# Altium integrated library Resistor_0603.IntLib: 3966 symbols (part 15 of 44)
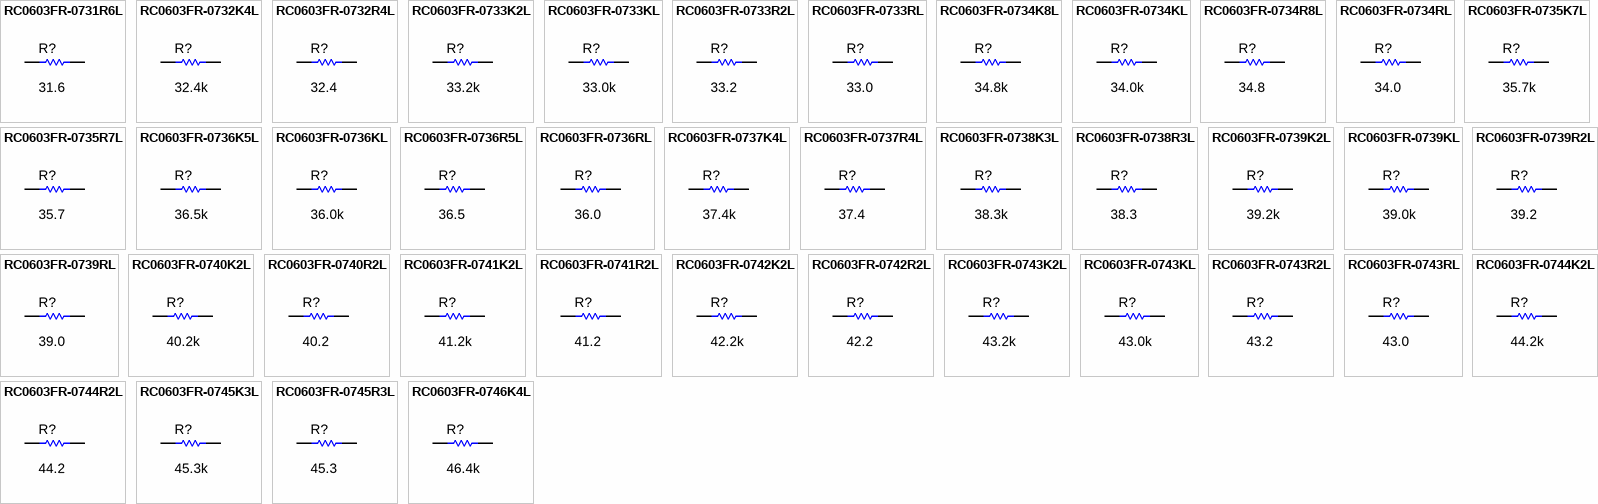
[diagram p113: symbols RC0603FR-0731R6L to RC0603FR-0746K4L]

## RC0603FR-0736RL
designator R?  ValueDisplayed: 36.0  (hidden comment: RC0603FR-0736RL)
RES, 36.0, 1%, 0.1 W, 0603; Manufacturer: Yageo America; CompType: Resistor; Value: 36.0; Res_ohm: 36; Value_Code: 36R0; Tolerance_%: 1; Power_W: 0.1; Value2: 0.1W; VDC_V: 150; TempCo: 200 ppm/C; SizeArea_mm2: 1.28; SizeX_mm: 1.6; SizeY_mm: 0.8; U/M: EA; AEC Category: Q200
signal-integrity model Resistor
simulation model Resistor
footprint 0603
footprint 0603M
footprint 0603L
footprint 0603_HV
footprint 0603S
pins: 1, 2

## RC0603FR-0737K4L
designator R?  ValueDisplayed: 37.4k  (hidden comment: RC0603FR-0737K4L)
RES, 37.4 k, 1%, 0.1 W, 0603; Manufacturer: Yageo America; CompType: Resistor; Value: 37.4k; Res_ohm: 37400; Value_Code: 37k4; Tolerance_%: 1; Power_W: 0.1; Value2: 0.1W; VDC_V: 150; TempCo: 200 ppm/C; SizeArea_mm2: 1.28; SizeX_mm: 1.6; SizeY_mm: 0.8; EIA_Code: E96; U/M: EA; AEC Category: Q200
signal-integrity model Resistor
simulation model Resistor
footprint 0603
footprint 0603M
footprint 0603L
footprint 0603_HV
footprint 0603S
pins: 1, 2

## RC0603FR-0737R4L
designator R?  ValueDisplayed: 37.4  (hidden comment: RC0603FR-0737R4L)
RES, 37.4, 1%, 0.1 W, 0603; Manufacturer: Yageo America; CompType: Resistor; Value: 37.4; Value_Code: 37R4; Tolerance_%: 1; Power_W: 0.1; Value2: 0.1W; VDC_V: 150; TempCo: 200 ppm/C; SizeArea_mm2: 1.28; SizeX_mm: 1.6; SizeY_mm: 0.8; EIA_Code: E96; U/M: EA; AEC Category: Q200
signal-integrity model Resistor
simulation model Resistor
footprint 0603
footprint 0603M
footprint 0603L
footprint 0603_HV
footprint 0603S
pins: 1, 2

## RC0603FR-0738K3L
designator R?  ValueDisplayed: 38.3k  (hidden comment: RC0603FR-0738K3L)
RES, 38.3 k, 1%, 0.1 W, 0603; Manufacturer: Yageo America; CompType: Resistor; Value: 38.3k; Res_ohm: 38300; Value_Code: 38k3; Tolerance_%: 1; Power_W: 0.1; Value2: 0.1W; VDC_V: 150; TempCo: 200 ppm/C; SizeArea_mm2: 1.28; SizeX_mm: 1.6; SizeY_mm: 0.8; EIA_Code: E96; U/M: EA; AEC Category: Q200; Green_Lifecycle: Active; Green_REACh: Passed
signal-integrity model Resistor
simulation model Resistor
footprint 0603
footprint 0603M
footprint 0603L
footprint 0603_HV
footprint 0603S
pins: 1, 2

## RC0603FR-0738R3L
designator R?  ValueDisplayed: 38.3  (hidden comment: RC0603FR-0738R3L)
RES, 38.3, 1%, 0.1 W, 0603; Manufacturer: Yageo America; CompType: Resistor; Value: 38.3; Value_Code: 38R3; Tolerance_%: 1; Power_W: 0.1; Value2: 0.1W; VDC_V: 150; TempCo: 200 ppm/C; SizeArea_mm2: 1.28; SizeX_mm: 1.6; SizeY_mm: 0.8; EIA_Code: E96; U/M: EA; AEC Category: Q200
signal-integrity model Resistor
simulation model Resistor
footprint 0603
footprint 0603M
footprint 0603L
footprint 0603_HV
footprint 0603S
pins: 1, 2

## RC0603FR-0739K2L
designator R?  ValueDisplayed: 39.2k  (hidden comment: RC0603FR-0739K2L)
RES, 39.2 k, 1%, 0.1 W, 0603; Manufacturer: Yageo America; CompType: Resistor; Value: 39.2k; Res_ohm: 39200; Value_Code: 39k2; Tolerance_%: 1; Power_W: 0.1; Value2: 0.1W; VDC_V: 150; TempCo: 200 ppm/C; SizeArea_mm2: 1.28; SizeX_mm: 1.6; SizeY_mm: 0.8; EIA_Code: E96; U/M: EA; AEC Category: Q200; Green_Lifecycle: Active; Green_REACh: Passed
signal-integrity model Resistor
simulation model Resistor
footprint 0603
footprint 0603M
footprint 0603L
footprint 0603_HV
footprint 0603S
pins: 1, 2

## RC0603FR-0739KL
designator R?  ValueDisplayed: 39.0k  (hidden comment: RC0603FR-0739KL)
RES, 39.0 k, 1%, 0.1 W, 0603; Manufacturer: Yageo America; CompType: Resistor; Value: 39.0k; Res_ohm: 39000; Value_Code: 39k0; Tolerance_%: 1; Power_W: 0.1; Value2: 0.1W; VDC_V: 150; TempCo: 200 ppm/C; SizeArea_mm2: 1.28; SizeX_mm: 1.6; SizeY_mm: 0.8; U/M: EA; AEC Category: Q200; Green_Lifecycle: Active; Green_REACh: Passed
signal-integrity model Resistor
simulation model Resistor
footprint 0603
footprint 0603M
footprint 0603L
footprint 0603_HV
footprint 0603S
pins: 1, 2

## RC0603FR-0739R2L
designator R?  ValueDisplayed: 39.2  (hidden comment: RC0603FR-0739R2L)
RES, 39.2, 1%, 0.1 W, 0603; Manufacturer: Yageo America; CompType: Resistor; Value: 39.2; Value_Code: 39R2; Tolerance_%: 1; Power_W: 0.1; Value2: 0.1W; VDC_V: 150; TempCo: 200 ppm/C; SizeArea_mm2: 1.28; SizeX_mm: 1.6; SizeY_mm: 0.8; EIA_Code: E96; U/M: EA; AEC Category: Q200
signal-integrity model Resistor
simulation model Resistor
footprint 0603
footprint 0603M
footprint 0603L
footprint 0603_HV
footprint 0603S
pins: 1, 2

## RC0603FR-0739RL
designator R?  ValueDisplayed: 39.0  (hidden comment: RC0603FR-0739RL)
RES, 39.0, 1%, 0.1 W, 0603; Manufacturer: Yageo America; CompType: Resistor; Value: 39.0; Res_ohm: 39; Value_Code: 39R0; Tolerance_%: 1; Power_W: 0.1; Value2: 0.1W; VDC_V: 150; TempCo: 200 ppm/C; SizeArea_mm2: 1.28; SizeX_mm: 1.6; SizeY_mm: 0.8; U/M: EA; AEC Category: Q200; Green_Lifecycle: Active; Green_REACh: Passed
signal-integrity model Resistor
simulation model Resistor
footprint 0603
footprint 0603M
footprint 0603L
footprint 0603_HV
footprint 0603S
pins: 1, 2

## RC0603FR-0740K2L
designator R?  ValueDisplayed: 40.2k  (hidden comment: RC0603FR-0740K2L)
RES, 40.2 k, 1%, 0.1 W, 0603; Manufacturer: Yageo America; CompType: Resistor; Value: 40.2k; Res_ohm: 40200; Value_Code: 40k2; Tolerance_%: 1; Power_W: 0.1; Value2: 0.1W; VDC_V: 150; TempCo: 200 ppm/C; SizeArea_mm2: 1.28; SizeX_mm: 1.6; SizeY_mm: 0.8; EIA_Code: E96; U/M: EA; AEC Category: Q200; Green_Lifecycle: Active; Green_REACh: Passed
signal-integrity model Resistor
simulation model Resistor
footprint 0603
footprint 0603M
footprint 0603L
footprint 0603_HV
footprint 0603S
pins: 1, 2

## RC0603FR-0740R2L
designator R?  ValueDisplayed: 40.2  (hidden comment: RC0603FR-0740R2L)
RES, 40.2, 1%, 0.1 W, 0603; Manufacturer: Yageo America; CompType: Resistor; Value: 40.2; Value_Code: 40R2; Tolerance_%: 1; Power_W: 0.1; Value2: 0.1W; VDC_V: 150; TempCo: 200 ppm/C; SizeArea_mm2: 1.28; SizeX_mm: 1.6; SizeY_mm: 0.8; EIA_Code: E96; U/M: EA; AEC Category: Q200
signal-integrity model Resistor
simulation model Resistor
footprint 0603
footprint 0603M
footprint 0603L
footprint 0603_HV
footprint 0603S
pins: 1, 2

## RC0603FR-0741K2L
designator R?  ValueDisplayed: 41.2k  (hidden comment: RC0603FR-0741K2L)
RES, 41.2 k, 1%, 0.1 W, 0603; Manufacturer: Yageo America; CompType: Resistor; Value: 41.2k; Res_ohm: 41200; Value_Code: 41k2; Tolerance_%: 1; Power_W: 0.1; Value2: 0.1W; VDC_V: 150; TempCo: 200 ppm/C; SizeArea_mm2: 1.28; SizeX_mm: 1.6; SizeY_mm: 0.8; EIA_Code: E96; U/M: EA; AEC Category: Q200; Green_Lifecycle: Active; Green_REACh: Passed
signal-integrity model Resistor
simulation model Resistor
footprint 0603
footprint 0603M
footprint 0603L
footprint 0603_HV
footprint 0603S
pins: 1, 2

## RC0603FR-0741R2L
designator R?  ValueDisplayed: 41.2  (hidden comment: RC0603FR-0741R2L)
RES, 41.2, 1%, 0.1 W, 0603; Manufacturer: Yageo America; CompType: Resistor; Value: 41.2; Value_Code: 41R2; Tolerance_%: 1; Power_W: 0.1; Value2: 0.1W; VDC_V: 150; TempCo: 200 ppm/C; SizeArea_mm2: 1.28; SizeX_mm: 1.6; SizeY_mm: 0.8; EIA_Code: E96; U/M: EA; AEC Category: Q200
signal-integrity model Resistor
simulation model Resistor
footprint 0603
footprint 0603M
footprint 0603L
footprint 0603_HV
footprint 0603S
pins: 1, 2

## RC0603FR-0742K2L
designator R?  ValueDisplayed: 42.2k  (hidden comment: RC0603FR-0742K2L)
RES, 42.2 k, 1%, 0.1 W, 0603; Manufacturer: Yageo America; CompType: Resistor; Value: 42.2k; Res_ohm: 42200; Value_Code: 42k2; Tolerance_%: 1; Power_W: 0.1; Value2: 0.1W; VDC_V: 150; TempCo: 200 ppm/C; SizeArea_mm2: 1.28; SizeX_mm: 1.6; SizeY_mm: 0.8; EIA_Code: E96; U/M: EA; AEC Category: Q200; Green_Lifecycle: Active; Green_REACh: Passed
signal-integrity model Resistor
simulation model Resistor
footprint 0603
footprint 0603M
footprint 0603L
footprint 0603_HV
footprint 0603S
pins: 1, 2

## RC0603FR-0742R2L
designator R?  ValueDisplayed: 42.2  (hidden comment: RC0603FR-0742R2L)
RES, 42.2, 1%, 0.1 W, 0603; Manufacturer: Yageo America; CompType: Resistor; Value: 42.2; Value_Code: 42R2; Tolerance_%: 1; Power_W: 0.1; Value2: 0.1W; VDC_V: 150; TempCo: 200 ppm/C; SizeArea_mm2: 1.28; SizeX_mm: 1.6; SizeY_mm: 0.8; EIA_Code: E96; U/M: EA; AEC Category: Q200
signal-integrity model Resistor
simulation model Resistor
footprint 0603
footprint 0603M
footprint 0603L
footprint 0603_HV
footprint 0603S
pins: 1, 2

## RC0603FR-0743K2L
designator R?  ValueDisplayed: 43.2k  (hidden comment: RC0603FR-0743K2L)
RES, 43.2 k, 1%, 0.1 W, 0603; Manufacturer: Yageo America; CompType: Resistor; Value: 43.2k; Res_ohm: 43200; Value_Code: 43k2; Tolerance_%: 1; Power_W: 0.1; Value2: 0.1W; VDC_V: 150; TempCo: 200 ppm/C; SizeArea_mm2: 1.28; SizeX_mm: 1.6; SizeY_mm: 0.8; EIA_Code: E96; U/M: EA; AEC Category: Q200; Green_Lifecycle: Active; Green_REACh: Passed
signal-integrity model Resistor
simulation model Resistor
footprint 0603
footprint 0603M
footprint 0603L
footprint 0603_HV
footprint 0603S
pins: 1, 2

## RC0603FR-0743KL
designator R?  ValueDisplayed: 43.0k  (hidden comment: RC0603FR-0743KL)
RES, 43.0 k, 1%, 0.1 W, 0603; Manufacturer: Yageo America; CompType: Resistor; Value: 43.0k; Res_ohm: 43000; Value_Code: 43k0; Tolerance_%: 1; Power_W: 0.1; Value2: 0.1W; VDC_V: 150; TempCo: 200 ppm/C; SizeArea_mm2: 1.28; SizeX_mm: 1.6; SizeY_mm: 0.8; U/M: EA; AEC Category: Q200; Green_Lifecycle: Active; Green_REACh: Passed
signal-integrity model Resistor
simulation model Resistor
footprint 0603
footprint 0603M
footprint 0603L
footprint 0603_HV
footprint 0603S
pins: 1, 2

## RC0603FR-0743R2L
designator R?  ValueDisplayed: 43.2  (hidden comment: RC0603FR-0743R2L)
RES, 43.2, 1%, 0.1 W, 0603; Manufacturer: Yageo America; CompType: Resistor; Value: 43.2; Value_Code: 43R2; Tolerance_%: 1; Power_W: 0.1; Value2: 0.1W; VDC_V: 150; TempCo: 200 ppm/C; SizeArea_mm2: 1.28; SizeX_mm: 1.6; SizeY_mm: 0.8; EIA_Code: E96; U/M: EA; AEC Category: Q200
signal-integrity model Resistor
simulation model Resistor
footprint 0603
footprint 0603M
footprint 0603L
footprint 0603_HV
footprint 0603S
pins: 1, 2

## RC0603FR-0743RL
designator R?  ValueDisplayed: 43.0  (hidden comment: RC0603FR-0743RL)
RES, 43.0, 1%, 0.1 W, 0603; Manufacturer: Yageo America; CompType: Resistor; Value: 43.0; Res_ohm: 43; Value_Code: 43R0; Tolerance_%: 1; Power_W: 0.1; Value2: 0.1W; VDC_V: 150; TempCo: 200 ppm/C; SizeArea_mm2: 1.28; SizeX_mm: 1.6; SizeY_mm: 0.8; U/M: EA; AEC Category: Q200; Green_Lifecycle: Active; Green_REACh: Passed
signal-integrity model Resistor
simulation model Resistor
footprint 0603
footprint 0603M
footprint 0603L
footprint 0603_HV
footprint 0603S
pins: 1, 2

## RC0603FR-0744K2L
designator R?  ValueDisplayed: 44.2k  (hidden comment: RC0603FR-0744K2L)
RES, 44.2 k, 1%, 0.1 W, 0603; Manufacturer: Yageo America; CompType: Resistor; Value: 44.2k; Res_ohm: 44200; Value_Code: 44k2; Tolerance_%: 1; Power_W: 0.1; Value2: 0.1W; VDC_V: 150; TempCo: 200 ppm/C; SizeArea_mm2: 1.28; SizeX_mm: 1.6; SizeY_mm: 0.8; EIA_Code: E96; U/M: EA; AEC Category: Q200; Green_Lifecycle: Active; Green_REACh: Passed
signal-integrity model Resistor
simulation model Resistor
footprint 0603
footprint 0603M
footprint 0603L
footprint 0603_HV
footprint 0603S
pins: 1, 2

## RC0603FR-0744R2L
designator R?  ValueDisplayed: 44.2  (hidden comment: RC0603FR-0744R2L)
RES, 44.2, 1%, 0.1 W, 0603; Manufacturer: Yageo America; CompType: Resistor; Value: 44.2; Value_Code: 44R2; Tolerance_%: 1; Power_W: 0.1; Value2: 0.1W; VDC_V: 150; TempCo: 200 ppm/C; SizeArea_mm2: 1.28; SizeX_mm: 1.6; SizeY_mm: 0.8; EIA_Code: E96; U/M: EA; AEC Category: Q200
signal-integrity model Resistor
simulation model Resistor
footprint 0603
footprint 0603M
footprint 0603L
footprint 0603_HV
footprint 0603S
pins: 1, 2

## RC0603FR-0745K3L
designator R?  ValueDisplayed: 45.3k  (hidden comment: RC0603FR-0745K3L)
RES, 45.3 k, 1%, 0.1 W, 0603; Manufacturer: Yageo America; CompType: Resistor; Value: 45.3k; Res_ohm: 45300; Value_Code: 45k3; Tolerance_%: 1; Power_W: 0.1; Value2: 0.1W; VDC_V: 150; TempCo: 200 ppm/C; SizeArea_mm2: 1.28; SizeX_mm: 1.6; SizeY_mm: 0.8; EIA_Code: E96; U/M: EA; AEC Category: Q200; Green_Lifecycle: Active; Green_REACh: Passed
signal-integrity model Resistor
simulation model Resistor
footprint 0603
footprint 0603M
footprint 0603L
footprint 0603_HV
footprint 0603S
pins: 1, 2

## RC0603FR-0745R3L
designator R?  ValueDisplayed: 45.3  (hidden comment: RC0603FR-0745R3L)
RES, 45.3, 1%, 0.1 W, 0603; Manufacturer: Yageo America; CompType: Resistor; Value: 45.3; Value_Code: 45R3; Tolerance_%: 1; Power_W: 0.1; Value2: 0.1W; VDC_V: 150; TempCo: 200 ppm/C; SizeArea_mm2: 1.28; SizeX_mm: 1.6; SizeY_mm: 0.8; EIA_Code: E96; U/M: EA; AEC Category: Q200
signal-integrity model Resistor
simulation model Resistor
footprint 0603
footprint 0603M
footprint 0603L
footprint 0603_HV
footprint 0603S
pins: 1, 2

## RC0603FR-0746K4L
designator R?  ValueDisplayed: 46.4k  (hidden comment: RC0603FR-0746K4L)
RES, 46.4 k, 1%, 0.1 W, 0603; Manufacturer: Yageo America; CompType: Resistor; Value: 46.4k; Res_ohm: 46400; Value_Code: 46k4; Tolerance_%: 1; Power_W: 0.1; Value2: 0.1W; VDC_V: 150; TempCo: 200 ppm/C; SizeArea_mm2: 1.28; SizeX_mm: 1.6; SizeY_mm: 0.8; EIA_Code: E96; U/M: EA; AEC Category: Q200; Green_Lifecycle: Active; Green_REACh: Passed
signal-integrity model Resistor
simulation model Resistor
footprint 0603
footprint 0603M
footprint 0603L
footprint 0603_HV
footprint 0603S
pins: 1, 2

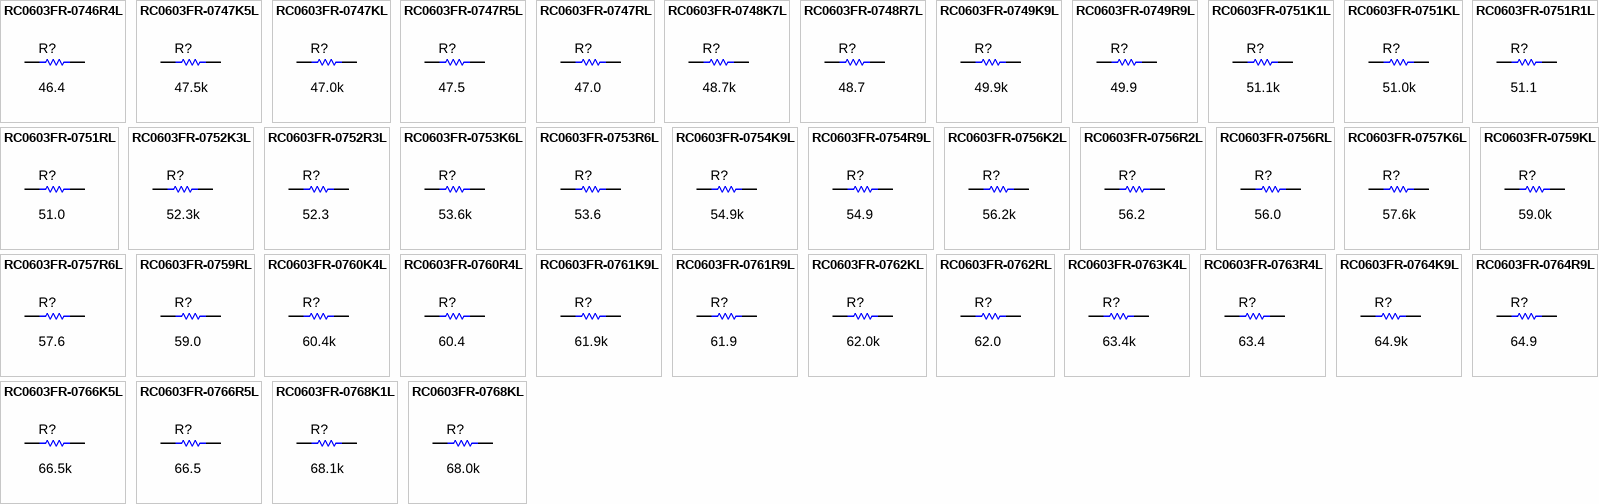
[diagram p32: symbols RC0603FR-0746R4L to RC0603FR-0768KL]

## RC0603FR-0746R4L
designator R?  ValueDisplayed: 46.4  (hidden comment: RC0603FR-0746R4L)
RES, 46.4, 1%, 0.1 W, 0603; Manufacturer: Yageo America; CompType: Resistor; Value: 46.4; Value_Code: 46R4; Tolerance_%: 1; Power_W: 0.1; Value2: 0.1W; VDC_V: 150; TempCo: 200 ppm/C; SizeArea_mm2: 1.28; SizeX_mm: 1.6; SizeY_mm: 0.8; EIA_Code: E96; U/M: EA; AEC Category: Q200
signal-integrity model Resistor
simulation model Resistor
footprint 0603
footprint 0603M
footprint 0603L
footprint 0603_HV
footprint 0603S
pins: 1, 2

## RC0603FR-0747K5L
designator R?  ValueDisplayed: 47.5k  (hidden comment: RC0603FR-0747K5L)
RES, 47.5 k, 1%, 0.1 W, 0603; Manufacturer: Yageo America; CompType: Resistor; Value: 47.5k; Res_ohm: 47500; Value_Code: 47k5; Tolerance_%: 1; Power_W: 0.1; Value2: 0.1W; VDC_V: 150; TempCo: 200 ppm/C; SizeArea_mm2: 1.28; SizeX_mm: 1.6; SizeY_mm: 0.8; EIA_Code: E96; U/M: EA; AEC Category: Q200; Green_Lifecycle: Active; Green_REACh: Passed
signal-integrity model Resistor
simulation model Resistor
footprint 0603
footprint 0603M
footprint 0603L
footprint 0603_HV
footprint 0603S
pins: 1, 2

## RC0603FR-0747KL
designator R?  ValueDisplayed: 47.0k  (hidden comment: RC0603FR-0747KL)
RES, 47.0 k, 1%, 0.1 W, 0603; Manufacturer: Yageo America; CompType: Resistor; Value: 47.0k; Res_ohm: 47000; Value_Code: 47k0; Tolerance_%: 1; Power_W: 0.1; Value2: 0.1W; VDC_V: 150; TempCo: 200 ppm/C; SizeArea_mm2: 1.28; SizeX_mm: 1.6; SizeY_mm: 0.8; U/M: EA; AEC Category: Q200; Green_Lifecycle: Active; Green_REACh: Passed
signal-integrity model Resistor
simulation model Resistor
footprint 0603
footprint 0603M
footprint 0603L
footprint 0603_HV
footprint 0603S
pins: 1, 2

## RC0603FR-0747R5L
designator R?  ValueDisplayed: 47.5  (hidden comment: RC0603FR-0747R5L)
RES, 47.5, 1%, 0.1 W, 0603; Manufacturer: Yageo America; CompType: Resistor; Value: 47.5; Value_Code: 47R5; Tolerance_%: 1; Power_W: 0.1; Value2: 0.1W; VDC_V: 150; TempCo: 200 ppm/C; SizeArea_mm2: 1.28; SizeX_mm: 1.6; SizeY_mm: 0.8; EIA_Code: E96; U/M: EA; AEC Category: Q200
signal-integrity model Resistor
simulation model Resistor
footprint 0603
footprint 0603M
footprint 0603L
footprint 0603_HV
footprint 0603S
pins: 1, 2

## RC0603FR-0747RL
designator R?  ValueDisplayed: 47.0  (hidden comment: RC0603FR-0747RL)
RES, 47.0, 1%, 0.1 W, 0603; Manufacturer: Yageo America; CompType: Resistor; Value: 47.0; Res_ohm: 47; Value_Code: 47R0; Tolerance_%: 1; Power_W: 0.1; Value2: 0.1W; VDC_V: 150; TempCo: 200 ppm/C; SizeArea_mm2: 1.28; SizeX_mm: 1.6; SizeY_mm: 0.8; U/M: EA; AEC Category: Q200; Green_Lifecycle: Active; Green_REACh: Passed
signal-integrity model Resistor
simulation model Resistor
footprint 0603
footprint 0603M
footprint 0603L
footprint 0603_HV
footprint 0603S
pins: 1, 2

## RC0603FR-0748K7L
designator R?  ValueDisplayed: 48.7k  (hidden comment: RC0603FR-0748K7L)
RES, 48.7 k, 1%, 0.1 W, 0603; Manufacturer: Yageo America; CompType: Resistor; Value: 48.7k; Res_ohm: 48700; Value_Code: 48k7; Tolerance_%: 1; Power_W: 0.1; Value2: 0.1W; VDC_V: 150; TempCo: 200 ppm/C; SizeArea_mm2: 1.28; SizeX_mm: 1.6; SizeY_mm: 0.8; EIA_Code: E96; U/M: EA; AEC Category: Q200; Green_Lifecycle: Active; Green_REACh: Passed
signal-integrity model Resistor
simulation model Resistor
footprint 0603
footprint 0603M
footprint 0603L
footprint 0603_HV
footprint 0603S
pins: 1, 2

## RC0603FR-0748R7L
designator R?  ValueDisplayed: 48.7  (hidden comment: RC0603FR-0748R7L)
RES, 48.7, 1%, 0.1 W, 0603; Manufacturer: Yageo America; CompType: Resistor; Value: 48.7; Value_Code: 48R7; Tolerance_%: 1; Power_W: 0.1; Value2: 0.1W; VDC_V: 150; TempCo: 200 ppm/C; SizeArea_mm2: 1.28; SizeX_mm: 1.6; SizeY_mm: 0.8; EIA_Code: E96; U/M: EA; AEC Category: Q200
signal-integrity model Resistor
simulation model Resistor
footprint 0603
footprint 0603M
footprint 0603L
footprint 0603_HV
footprint 0603S
pins: 1, 2

## RC0603FR-0749K9L
designator R?  ValueDisplayed: 49.9k  (hidden comment: RC0603FR-0749K9L)
RES, 49.9 k, 1%, 0.1 W, 0603; Manufacturer: Yageo America; CompType: Resistor; Value: 49.9k; Res_ohm: 49900; Value_Code: 49k9; Tolerance_%: 1; Power_W: 0.1; Value2: 0.1W; VDC_V: 150; TempCo: 200 ppm/C; SizeArea_mm2: 1.28; SizeX_mm: 1.6; SizeY_mm: 0.8; EIA_Code: E96; U/M: EA; AEC Category: Q200; Green_Lifecycle: Active; Green_REACh: Passed
signal-integrity model Resistor
simulation model Resistor
footprint 0603
footprint 0603M
footprint 0603L
footprint 0603_HV
footprint 0603S
pins: 1, 2

## RC0603FR-0749R9L
designator R?  ValueDisplayed: 49.9  (hidden comment: RC0603FR-0749R9L)
RES, 49.9, 1%, 0.1 W, 0603; Manufacturer: Yageo America; CompType: Resistor; Value: 49.9; Value_Code: 49R9; Tolerance_%: 1; Power_W: 0.1; Value2: 0.1W; VDC_V: 150; TempCo: 200 ppm/C; SizeArea_mm2: 1.28; SizeX_mm: 1.6; SizeY_mm: 0.8; EIA_Code: E96; U/M: EA; AEC Category: Q200; Green_Lifecycle: Active; Green_REACh: Passed
signal-integrity model Resistor
simulation model Resistor
footprint 0603
footprint 0603M
footprint 0603L
footprint 0603_HV
footprint 0603S
pins: 1, 2

## RC0603FR-0751K1L
designator R?  ValueDisplayed: 51.1k  (hidden comment: RC0603FR-0751K1L)
RES, 51.1 k, 1%, 0.1 W, 0603; Manufacturer: Yageo America; CompType: Resistor; Value: 51.1k; Res_ohm: 51100; Value_Code: 51k1; Tolerance_%: 1; Power_W: 0.1; Value2: 0.1W; VDC_V: 150; TempCo: 200 ppm/C; SizeArea_mm2: 1.28; SizeX_mm: 1.6; SizeY_mm: 0.8; EIA_Code: E96; U/M: EA; AEC Category: Q200; Green_Lifecycle: Active; Green_REACh: Passed
signal-integrity model Resistor
simulation model Resistor
footprint 0603
footprint 0603M
footprint 0603L
footprint 0603_HV
footprint 0603S
pins: 1, 2

## RC0603FR-0751KL
designator R?  ValueDisplayed: 51.0k  (hidden comment: RC0603FR-0751KL)
RES, 51.0 k, 1%, 0.1 W, 0603; Manufacturer: Yageo America; CompType: Resistor; Value: 51.0k; Res_ohm: 51000; Value_Code: 51k0; Tolerance_%: 1; Power_W: 0.1; Value2: 0.1W; VDC_V: 150; TempCo: 200 ppm/C; SizeArea_mm2: 1.28; SizeX_mm: 1.6; SizeY_mm: 0.8; U/M: EA; AEC Category: Q200; Green_Lifecycle: Active; Green_REACh: Passed
signal-integrity model Resistor
simulation model Resistor
footprint 0603
footprint 0603M
footprint 0603L
footprint 0603_HV
footprint 0603S
pins: 1, 2

## RC0603FR-0751R1L
designator R?  ValueDisplayed: 51.1  (hidden comment: RC0603FR-0751R1L)
RES, 51.1, 1%, 0.1 W, 0603; Manufacturer: Yageo America; CompType: Resistor; Value: 51.1; Value_Code: 51R1; Tolerance_%: 1; Power_W: 0.1; Value2: 0.1W; VDC_V: 150; TempCo: 200 ppm/C; SizeArea_mm2: 1.28; SizeX_mm: 1.6; SizeY_mm: 0.8; EIA_Code: E96; U/M: EA; AEC Category: Q200; Green_Lifecycle: Active; Green_REACh: Passed
signal-integrity model Resistor
simulation model Resistor
footprint 0603
footprint 0603M
footprint 0603L
footprint 0603_HV
footprint 0603S
pins: 1, 2

## RC0603FR-0751RL
designator R?  ValueDisplayed: 51.0  (hidden comment: RC0603FR-0751RL)
RES, 51.0, 1%, 0.1 W, 0603; Manufacturer: Yageo America; CompType: Resistor; Value: 51.0; Res_ohm: 51; Value_Code: 51R0; Tolerance_%: 1; Power_W: 0.1; Value2: 0.1W; VDC_V: 150; TempCo: 200 ppm/C; SizeArea_mm2: 1.28; SizeX_mm: 1.6; SizeY_mm: 0.8; U/M: EA; AEC Category: Q200; Green_Lifecycle: Active; Green_REACh: Passed
signal-integrity model Resistor
simulation model Resistor
footprint 0603
footprint 0603M
footprint 0603L
footprint 0603_HV
footprint 0603S
pins: 1, 2

## RC0603FR-0752K3L
designator R?  ValueDisplayed: 52.3k  (hidden comment: RC0603FR-0752K3L)
RES, 52.3 k, 1%, 0.1 W, 0603; Manufacturer: Yageo America; CompType: Resistor; Value: 52.3k; Res_ohm: 52300; Value_Code: 52k3; Tolerance_%: 1; Power_W: 0.1; Value2: 0.1W; VDC_V: 150; TempCo: 200 ppm/C; SizeArea_mm2: 1.28; SizeX_mm: 1.6; SizeY_mm: 0.8; EIA_Code: E96; U/M: EA; AEC Category: Q200; Green_Lifecycle: Active; Green_REACh: Passed
signal-integrity model Resistor
simulation model Resistor
footprint 0603
footprint 0603M
footprint 0603L
footprint 0603_HV
footprint 0603S
pins: 1, 2

## RC0603FR-0752R3L
designator R?  ValueDisplayed: 52.3  (hidden comment: RC0603FR-0752R3L)
RES, 52.3, 1%, 0.1 W, 0603; Manufacturer: Yageo America; CompType: Resistor; Value: 52.3; Value_Code: 52R3; Tolerance_%: 1; Power_W: 0.1; Value2: 0.1W; VDC_V: 150; TempCo: 200 ppm/C; SizeArea_mm2: 1.28; SizeX_mm: 1.6; SizeY_mm: 0.8; EIA_Code: E96; U/M: EA; AEC Category: Q200
signal-integrity model Resistor
simulation model Resistor
footprint 0603
footprint 0603M
footprint 0603L
footprint 0603_HV
footprint 0603S
pins: 1, 2

## RC0603FR-0753K6L
designator R?  ValueDisplayed: 53.6k  (hidden comment: RC0603FR-0753K6L)
RES, 53.6 k, 1%, 0.1 W, 0603; Manufacturer: Yageo America; CompType: Resistor; Value: 53.6k; Res_ohm: 53600; Value_Code: 53k6; Tolerance_%: 1; Power_W: 0.1; Value2: 0.1W; VDC_V: 150; TempCo: 200 ppm/C; SizeArea_mm2: 1.28; SizeX_mm: 1.6; SizeY_mm: 0.8; EIA_Code: E96; U/M: EA; AEC Category: Q200; Green_Lifecycle: Active; Green_REACh: Passed
signal-integrity model Resistor
simulation model Resistor
footprint 0603
footprint 0603M
footprint 0603L
footprint 0603_HV
footprint 0603S
pins: 1, 2

## RC0603FR-0753R6L
designator R?  ValueDisplayed: 53.6  (hidden comment: RC0603FR-0753R6L)
RES, 53.6, 1%, 0.1 W, 0603; Manufacturer: Yageo America; CompType: Resistor; Value: 53.6; Value_Code: 53R6; Tolerance_%: 1; Power_W: 0.1; Value2: 0.1W; VDC_V: 150; TempCo: 200 ppm/C; SizeArea_mm2: 1.28; SizeX_mm: 1.6; SizeY_mm: 0.8; EIA_Code: E96; U/M: EA; AEC Category: Q200
signal-integrity model Resistor
simulation model Resistor
footprint 0603
footprint 0603M
footprint 0603L
footprint 0603_HV
footprint 0603S
pins: 1, 2

## RC0603FR-0754K9L
designator R?  ValueDisplayed: 54.9k  (hidden comment: RC0603FR-0754K9L)
RES, 54.9 k, 1%, 0.1 W, 0603; Manufacturer: Yageo America; CompType: Resistor; Value: 54.9k; Res_ohm: 54900; Value_Code: 54k9; Tolerance_%: 1; Power_W: 0.1; Value2: 0.1W; VDC_V: 150; TempCo: 200 ppm/C; SizeArea_mm2: 1.28; SizeX_mm: 1.6; SizeY_mm: 0.8; EIA_Code: E96; U/M: EA; AEC Category: Q200
signal-integrity model Resistor
simulation model Resistor
footprint 0603
footprint 0603M
footprint 0603L
footprint 0603_HV
footprint 0603S
pins: 1, 2

## RC0603FR-0754R9L
designator R?  ValueDisplayed: 54.9  (hidden comment: RC0603FR-0754R9L)
RES, 54.9, 1%, 0.1 W, 0603; Manufacturer: Yageo America; CompType: Resistor; Value: 54.9; Value_Code: 54R9; Tolerance_%: 1; Power_W: 0.1; Value2: 0.1W; VDC_V: 150; TempCo: 200 ppm/C; SizeArea_mm2: 1.28; SizeX_mm: 1.6; SizeY_mm: 0.8; EIA_Code: E96; U/M: EA; AEC Category: Q200; Green_Lifecycle: Active; Green_REACh: Passed
signal-integrity model Resistor
simulation model Resistor
footprint 0603
footprint 0603M
footprint 0603L
footprint 0603_HV
footprint 0603S
pins: 1, 2

## RC0603FR-0756K2L
designator R?  ValueDisplayed: 56.2k  (hidden comment: RC0603FR-0756K2L)
RES, 56.2 k, 1%, 0.1 W, 0603; Manufacturer: Yageo America; CompType: Resistor; Value: 56.2k; Res_ohm: 56200; Value_Code: 56k2; Tolerance_%: 1; Power_W: 0.1; Value2: 0.1W; VDC_V: 150; TempCo: 200 ppm/C; SizeArea_mm2: 1.28; SizeX_mm: 1.6; SizeY_mm: 0.8; EIA_Code: E96; U/M: EA; AEC Category: Q200; Green_Lifecycle: Active; Green_REACh: Passed
signal-integrity model Resistor
simulation model Resistor
footprint 0603
footprint 0603M
footprint 0603L
footprint 0603_HV
footprint 0603S
pins: 1, 2

## RC0603FR-0756R2L
designator R?  ValueDisplayed: 56.2  (hidden comment: RC0603FR-0756R2L)
RES, 56.2, 1%, 0.1 W, 0603; Manufacturer: Yageo America; CompType: Resistor; Value: 56.2; Value_Code: 56R2; Tolerance_%: 1; Power_W: 0.1; Value2: 0.1W; VDC_V: 150; TempCo: 200 ppm/C; SizeArea_mm2: 1.28; SizeX_mm: 1.6; SizeY_mm: 0.8; EIA_Code: E96; U/M: EA; AEC Category: Q200
signal-integrity model Resistor
simulation model Resistor
footprint 0603
footprint 0603M
footprint 0603L
footprint 0603_HV
footprint 0603S
pins: 1, 2

## RC0603FR-0756RL
designator R?  ValueDisplayed: 56.0  (hidden comment: RC0603FR-0756RL)
RES, 56.0, 1%, 0.1 W, 0603; Manufacturer: Yageo America; CompType: Resistor; Value: 56.0; Res_ohm: 56; Value_Code: 56R0; Tolerance_%: 1; Power_W: 0.1; Value2: 0.1W; VDC_V: 150; TempCo: 200 ppm/C; SizeArea_mm2: 1.28; SizeX_mm: 1.6; SizeY_mm: 0.8; U/M: EA; AEC Category: Q200; Green_Lifecycle: Active; Green_REACh: Passed
signal-integrity model Resistor
simulation model Resistor
footprint 0603
footprint 0603M
footprint 0603L
footprint 0603_HV
footprint 0603S
pins: 1, 2

## RC0603FR-0757K6L
designator R?  ValueDisplayed: 57.6k  (hidden comment: RC0603FR-0757K6L)
RES, 57.6 k, 1%, 0.1 W, 0603; Manufacturer: Yageo America; CompType: Resistor; Value: 57.6k; Res_ohm: 57600; Value_Code: 57k6; Tolerance_%: 1; Power_W: 0.1; Value2: 0.1W; VDC_V: 150; TempCo: 200 ppm/C; SizeArea_mm2: 1.28; SizeX_mm: 1.6; SizeY_mm: 0.8; EIA_Code: E96; U/M: EA; AEC Category: Q200; Green_Lifecycle: Active; Green_REACh: Passed
signal-integrity model Resistor
simulation model Resistor
footprint 0603
footprint 0603M
footprint 0603L
footprint 0603_HV
footprint 0603S
pins: 1, 2

## RC0603FR-0757R6L
designator R?  ValueDisplayed: 57.6  (hidden comment: RC0603FR-0757R6L)
RES, 57.6, 1%, 0.1 W, 0603; Manufacturer: Yageo America; CompType: Resistor; Value: 57.6; Value_Code: 57R6; Tolerance_%: 1; Power_W: 0.1; Value2: 0.1W; VDC_V: 150; TempCo: 200 ppm/C; SizeArea_mm2: 1.28; SizeX_mm: 1.6; SizeY_mm: 0.8; EIA_Code: E96; U/M: EA; AEC Category: Q200
signal-integrity model Resistor
simulation model Resistor
footprint 0603
footprint 0603M
footprint 0603L
footprint 0603_HV
footprint 0603S
pins: 1, 2

## RC0603FR-0759KL
designator R?  ValueDisplayed: 59.0k  (hidden comment: RC0603FR-0759KL)
RES, 59.0 k, 1%, 0.1 W, 0603; Manufacturer: Yageo America; CompType: Resistor; Value: 59.0k; Res_ohm: 59000; Value_Code: 59k0; Tolerance_%: 1; Power_W: 0.1; Value2: 0.1W; VDC_V: 150; TempCo: 200 ppm/C; SizeArea_mm2: 1.28; SizeX_mm: 1.6; SizeY_mm: 0.8; EIA_Code: E96; U/M: EA; AEC Category: Q200; Green_Lifecycle: Active; Green_REACh: Passed
signal-integrity model Resistor
simulation model Resistor
footprint 0603
footprint 0603M
footprint 0603L
footprint 0603_HV
footprint 0603S
pins: 1, 2

## RC0603FR-0759RL
designator R?  ValueDisplayed: 59.0  (hidden comment: RC0603FR-0759RL)
RES, 59.0, 1%, 0.1 W, 0603; Manufacturer: Yageo America; CompType: Resistor; Value: 59.0; Res_ohm: 59; Value_Code: 59R0; Tolerance_%: 1; Power_W: 0.1; Value2: 0.1W; VDC_V: 150; TempCo: 200 ppm/C; SizeArea_mm2: 1.28; SizeX_mm: 1.6; SizeY_mm: 0.8; EIA_Code: E96; U/M: EA; AEC Category: Q200
signal-integrity model Resistor
simulation model Resistor
footprint 0603
footprint 0603M
footprint 0603L
footprint 0603_HV
footprint 0603S
pins: 1, 2

## RC0603FR-0760K4L
designator R?  ValueDisplayed: 60.4k  (hidden comment: RC0603FR-0760K4L)
RES, 60.4 k, 1%, 0.1 W, 0603; Manufacturer: Yageo America; CompType: Resistor; Value: 60.4k; Res_ohm: 60400; Value_Code: 60k4; Tolerance_%: 1; Power_W: 0.1; Value2: 0.1W; VDC_V: 150; TempCo: 200 ppm/C; SizeArea_mm2: 1.28; SizeX_mm: 1.6; SizeY_mm: 0.8; EIA_Code: E96; U/M: EA; AEC Category: Q200; Green_Lifecycle: Active; Green_REACh: Passed
signal-integrity model Resistor
simulation model Resistor
footprint 0603
footprint 0603M
footprint 0603L
footprint 0603_HV
footprint 0603S
pins: 1, 2

## RC0603FR-0760R4L
designator R?  ValueDisplayed: 60.4  (hidden comment: RC0603FR-0760R4L)
RES, 60.4, 1%, 0.1 W, 0603; Manufacturer: Yageo America; CompType: Resistor; Value: 60.4; Value_Code: 60R4; Tolerance_%: 1; Power_W: 0.1; Value2: 0.1W; VDC_V: 150; TempCo: 200 ppm/C; SizeArea_mm2: 1.28; SizeX_mm: 1.6; SizeY_mm: 0.8; EIA_Code: E96; U/M: EA; AEC Category: Q200
signal-integrity model Resistor
simulation model Resistor
footprint 0603
footprint 0603M
footprint 0603L
footprint 0603_HV
footprint 0603S
pins: 1, 2

## RC0603FR-0761K9L
designator R?  ValueDisplayed: 61.9k  (hidden comment: RC0603FR-0761K9L)
RES, 61.9 k, 1%, 0.1 W, 0603; Manufacturer: Yageo America; CompType: Resistor; Value: 61.9k; Res_ohm: 61900; Value_Code: 61k9; Tolerance_%: 1; Power_W: 0.1; Value2: 0.1W; VDC_V: 150; TempCo: 200 ppm/C; SizeArea_mm2: 1.28; SizeX_mm: 1.6; SizeY_mm: 0.8; EIA_Code: E96; U/M: EA; AEC Category: Q200
signal-integrity model Resistor
simulation model Resistor
footprint 0603
footprint 0603M
footprint 0603L
footprint 0603_HV
footprint 0603S
pins: 1, 2

## RC0603FR-0761R9L
designator R?  ValueDisplayed: 61.9  (hidden comment: RC0603FR-0761R9L)
RES, 61.9, 1%, 0.1 W, 0603; Manufacturer: Yageo America; CompType: Resistor; Value: 61.9; Value_Code: 61R9; Tolerance_%: 1; Power_W: 0.1; Value2: 0.1W; VDC_V: 150; TempCo: 200 ppm/C; SizeArea_mm2: 1.28; SizeX_mm: 1.6; SizeY_mm: 0.8; EIA_Code: E96; U/M: EA; AEC Category: Q200
signal-integrity model Resistor
simulation model Resistor
footprint 0603
footprint 0603M
footprint 0603L
footprint 0603_HV
footprint 0603S
pins: 1, 2

## RC0603FR-0762KL
designator R?  ValueDisplayed: 62.0k  (hidden comment: RC0603FR-0762KL)
RES, 62.0 k, 1%, 0.1 W, 0603; Manufacturer: Yageo America; CompType: Resistor; Value: 62.0k; Res_ohm: 62000; Value_Code: 62k0; Tolerance_%: 1; Power_W: 0.1; Value2: 0.1W; VDC_V: 150; TempCo: 200 ppm/C; SizeArea_mm2: 1.28; SizeX_mm: 1.6; SizeY_mm: 0.8; U/M: EA; AEC Category: Q200; Green_Lifecycle: Active; Green_REACh: Passed
signal-integrity model Resistor
simulation model Resistor
footprint 0603
footprint 0603M
footprint 0603L
footprint 0603_HV
footprint 0603S
pins: 1, 2

## RC0603FR-0762RL
designator R?  ValueDisplayed: 62.0  (hidden comment: RC0603FR-0762RL)
RES, 62.0, 1%, 0.1 W, 0603; Manufacturer: Yageo America; CompType: Resistor; Value: 62.0; Res_ohm: 62; Value_Code: 62R0; Tolerance_%: 1; Power_W: 0.1; Value2: 0.1W; VDC_V: 150; TempCo: 200 ppm/C; SizeArea_mm2: 1.28; SizeX_mm: 1.6; SizeY_mm: 0.8; U/M: EA; AEC Category: Q200
signal-integrity model Resistor
simulation model Resistor
footprint 0603
footprint 0603M
footprint 0603L
footprint 0603_HV
footprint 0603S
pins: 1, 2

## RC0603FR-0763K4L
designator R?  ValueDisplayed: 63.4k  (hidden comment: RC0603FR-0763K4L)
RES, 63.4 k, 1%, 0.1 W, 0603; Manufacturer: Yageo America; CompType: Resistor; Value: 63.4k; Res_ohm: 63400; Value_Code: 63k4; Tolerance_%: 1; Power_W: 0.1; Value2: 0.1W; VDC_V: 150; TempCo: 200 ppm/C; SizeArea_mm2: 1.28; SizeX_mm: 1.6; SizeY_mm: 0.8; EIA_Code: E96; U/M: EA; AEC Category: Q200
signal-integrity model Resistor
simulation model Resistor
footprint 0603
footprint 0603M
footprint 0603L
footprint 0603_HV
footprint 0603S
pins: 1, 2

## RC0603FR-0763R4L
designator R?  ValueDisplayed: 63.4  (hidden comment: RC0603FR-0763R4L)
RES, 63.4, 1%, 0.1 W, 0603; Manufacturer: Yageo America; CompType: Resistor; Value: 63.4; Value_Code: 63R4; Tolerance_%: 1; Power_W: 0.1; Value2: 0.1W; VDC_V: 150; TempCo: 200 ppm/C; SizeArea_mm2: 1.28; SizeX_mm: 1.6; SizeY_mm: 0.8; EIA_Code: E96; U/M: EA; AEC Category: Q200
signal-integrity model Resistor
simulation model Resistor
footprint 0603
footprint 0603M
footprint 0603L
footprint 0603_HV
footprint 0603S
pins: 1, 2

## RC0603FR-0764K9L
designator R?  ValueDisplayed: 64.9k  (hidden comment: RC0603FR-0764K9L)
RES, 64.9 k, 1%, 0.1 W, 0603; Manufacturer: Yageo America; CompType: Resistor; Value: 64.9k; Res_ohm: 64900; Value_Code: 64k9; Tolerance_%: 1; Power_W: 0.1; Value2: 0.1W; VDC_V: 150; TempCo: 200 ppm/C; SizeArea_mm2: 1.28; SizeX_mm: 1.6; SizeY_mm: 0.8; EIA_Code: E96; U/M: EA; AEC Category: Q200
signal-integrity model Resistor
simulation model Resistor
footprint 0603
footprint 0603M
footprint 0603L
footprint 0603_HV
footprint 0603S
pins: 1, 2

## RC0603FR-0764R9L
designator R?  ValueDisplayed: 64.9  (hidden comment: RC0603FR-0764R9L)
RES, 64.9, 1%, 0.1 W, 0603; Manufacturer: Yageo America; CompType: Resistor; Value: 64.9; Value_Code: 64R9; Tolerance_%: 1; Power_W: 0.1; Value2: 0.1W; VDC_V: 150; TempCo: 200 ppm/C; SizeArea_mm2: 1.28; SizeX_mm: 1.6; SizeY_mm: 0.8; EIA_Code: E96; U/M: EA; AEC Category: Q200
signal-integrity model Resistor
simulation model Resistor
footprint 0603
footprint 0603M
footprint 0603L
footprint 0603_HV
footprint 0603S
pins: 1, 2

## RC0603FR-0766K5L
designator R?  ValueDisplayed: 66.5k  (hidden comment: RC0603FR-0766K5L)
RES, 66.5 k, 1%, 0.1 W, 0603; Manufacturer: Yageo America; CompType: Resistor; Value: 66.5k; Res_ohm: 66500; Value_Code: 66k5; Tolerance_%: 1; Power_W: 0.1; Value2: 0.1W; VDC_V: 150; TempCo: 200 ppm/C; SizeArea_mm2: 1.28; SizeX_mm: 1.6; SizeY_mm: 0.8; EIA_Code: E96; U/M: EA; AEC Category: Q200
signal-integrity model Resistor
simulation model Resistor
footprint 0603
footprint 0603M
footprint 0603L
footprint 0603_HV
footprint 0603S
pins: 1, 2

## RC0603FR-0766R5L
designator R?  ValueDisplayed: 66.5  (hidden comment: RC0603FR-0766R5L)
RES, 66.5, 1%, 0.1 W, 0603; Manufacturer: Yageo America; CompType: Resistor; Value: 66.5; Value_Code: 66R5; Tolerance_%: 1; Power_W: 0.1; Value2: 0.1W; VDC_V: 150; TempCo: 200 ppm/C; SizeArea_mm2: 1.28; SizeX_mm: 1.6; SizeY_mm: 0.8; EIA_Code: E96; U/M: EA; AEC Category: Q200
signal-integrity model Resistor
simulation model Resistor
footprint 0603
footprint 0603M
footprint 0603L
footprint 0603_HV
footprint 0603S
pins: 1, 2

## RC0603FR-0768K1L
designator R?  ValueDisplayed: 68.1k  (hidden comment: RC0603FR-0768K1L)
RES, 68.1 k, 1%, 0.1 W, 0603; Manufacturer: Yageo America; CompType: Resistor; Value: 68.1k; Res_ohm: 68100; Value_Code: 68k1; Tolerance_%: 1; Power_W: 0.1; Value2: 0.1W; VDC_V: 150; TempCo: 200 ppm/C; SizeArea_mm2: 1.28; SizeX_mm: 1.6; SizeY_mm: 0.8; EIA_Code: E96; U/M: EA; AEC Category: Q200
signal-integrity model Resistor
simulation model Resistor
footprint 0603
footprint 0603M
footprint 0603L
footprint 0603_HV
footprint 0603S
pins: 1, 2

## RC0603FR-0768KL
designator R?  ValueDisplayed: 68.0k  (hidden comment: RC0603FR-0768KL)
RES, 68.0 k, 1%, 0.1 W, 0603; Manufacturer: Yageo America; CompType: Resistor; Value: 68.0k; Res_ohm: 68000; Value_Code: 68k0; Tolerance_%: 1; Power_W: 0.1; Value2: 0.1W; VDC_V: 150; TempCo: 200 ppm/C; SizeArea_mm2: 1.28; SizeX_mm: 1.6; SizeY_mm: 0.8; U/M: EA; AEC Category: Q200; Green_Lifecycle: Active; Green_REACh: Passed
signal-integrity model Resistor
simulation model Resistor
footprint 0603
footprint 0603M
footprint 0603L
footprint 0603_HV
footprint 0603S
pins: 1, 2

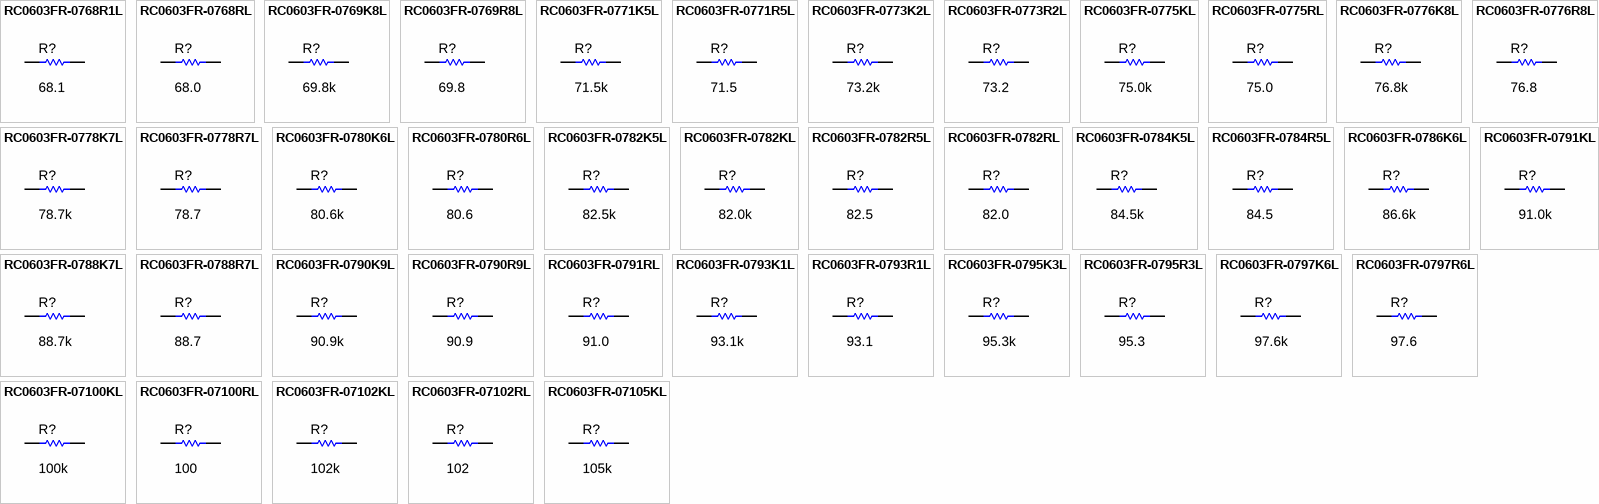
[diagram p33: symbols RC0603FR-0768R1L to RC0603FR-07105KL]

## RC0603FR-0768R1L
designator R?  ValueDisplayed: 68.1  (hidden comment: RC0603FR-0768R1L)
RES, 68.1, 1%, 0.1 W, 0603; Manufacturer: Yageo America; CompType: Resistor; Value: 68.1; Value_Code: 68R1; Tolerance_%: 1; Power_W: 0.1; Value2: 0.1W; VDC_V: 150; TempCo: 200 ppm/C; SizeArea_mm2: 1.28; SizeX_mm: 1.6; SizeY_mm: 0.8; EIA_Code: E96; U/M: EA; AEC Category: Q200; Green_Lifecycle: Active; Green_REACh: Passed
signal-integrity model Resistor
simulation model Resistor
footprint 0603
footprint 0603M
footprint 0603L
footprint 0603_HV
footprint 0603S
pins: 1, 2

## RC0603FR-0768RL
designator R?  ValueDisplayed: 68.0  (hidden comment: RC0603FR-0768RL)
RES, 68.0, 1%, 0.1 W, 0603; Manufacturer: Yageo America; CompType: Resistor; Value: 68.0; Res_ohm: 68; Value_Code: 68R0; Tolerance_%: 1; Power_W: 0.1; Value2: 0.1W; VDC_V: 150; TempCo: 200 ppm/C; SizeArea_mm2: 1.28; SizeX_mm: 1.6; SizeY_mm: 0.8; U/M: EA; AEC Category: Q200
signal-integrity model Resistor
simulation model Resistor
footprint 0603
footprint 0603M
footprint 0603L
footprint 0603_HV
footprint 0603S
pins: 1, 2

## RC0603FR-0769K8L
designator R?  ValueDisplayed: 69.8k  (hidden comment: RC0603FR-0769K8L)
RES, 69.8 k, 1%, 0.1 W, 0603; Manufacturer: Yageo America; CompType: Resistor; Value: 69.8k; Res_ohm: 69800; Value_Code: 69k8; Tolerance_%: 1; Power_W: 0.1; Value2: 0.1W; VDC_V: 150; TempCo: 200 ppm/C; SizeArea_mm2: 1.28; SizeX_mm: 1.6; SizeY_mm: 0.8; EIA_Code: E96; U/M: EA; AEC Category: Q200
signal-integrity model Resistor
simulation model Resistor
footprint 0603
footprint 0603M
footprint 0603L
footprint 0603_HV
footprint 0603S
pins: 1, 2

## RC0603FR-0769R8L
designator R?  ValueDisplayed: 69.8  (hidden comment: RC0603FR-0769R8L)
RES, 69.8, 1%, 0.1 W, 0603; Manufacturer: Yageo America; CompType: Resistor; Value: 69.8; Value_Code: 69R8; Tolerance_%: 1; Power_W: 0.1; Value2: 0.1W; VDC_V: 150; TempCo: 200 ppm/C; SizeArea_mm2: 1.28; SizeX_mm: 1.6; SizeY_mm: 0.8; EIA_Code: E96; U/M: EA; AEC Category: Q200
signal-integrity model Resistor
simulation model Resistor
footprint 0603
footprint 0603M
footprint 0603L
footprint 0603_HV
footprint 0603S
pins: 1, 2

## RC0603FR-0771K5L
designator R?  ValueDisplayed: 71.5k  (hidden comment: RC0603FR-0771K5L)
RES, 71.5 k, 1%, 0.1 W, 0603; Manufacturer: Yageo America; CompType: Resistor; Value: 71.5k; Res_ohm: 71500; Value_Code: 71k5; Tolerance_%: 1; Power_W: 0.1; Value2: 0.1W; VDC_V: 150; TempCo: 200 ppm/C; SizeArea_mm2: 1.28; SizeX_mm: 1.6; SizeY_mm: 0.8; EIA_Code: E96; U/M: EA; AEC Category: Q200; Green_Lifecycle: Active; Green_REACh: Passed
signal-integrity model Resistor
simulation model Resistor
footprint 0603
footprint 0603M
footprint 0603L
footprint 0603_HV
footprint 0603S
pins: 1, 2

## RC0603FR-0771R5L
designator R?  ValueDisplayed: 71.5  (hidden comment: RC0603FR-0771R5L)
RES, 71.5, 1%, 0.1 W, 0603; Manufacturer: Yageo America; CompType: Resistor; Value: 71.5; Value_Code: 71R5; Tolerance_%: 1; Power_W: 0.1; Value2: 0.1W; VDC_V: 150; TempCo: 200 ppm/C; SizeArea_mm2: 1.28; SizeX_mm: 1.6; SizeY_mm: 0.8; EIA_Code: E96; U/M: EA; AEC Category: Q200
signal-integrity model Resistor
simulation model Resistor
footprint 0603
footprint 0603M
footprint 0603L
footprint 0603_HV
footprint 0603S
pins: 1, 2

## RC0603FR-0773K2L
designator R?  ValueDisplayed: 73.2k  (hidden comment: RC0603FR-0773K2L)
RES, 73.2 k, 1%, 0.1 W, 0603; Manufacturer: Yageo America; CompType: Resistor; Value: 73.2k; Res_ohm: 73200; Value_Code: 73k2; Tolerance_%: 1; Power_W: 0.1; Value2: 0.1W; VDC_V: 150; TempCo: 200 ppm/C; SizeArea_mm2: 1.28; SizeX_mm: 1.6; SizeY_mm: 0.8; EIA_Code: E96; U/M: EA; AEC Category: Q200
signal-integrity model Resistor
simulation model Resistor
footprint 0603
footprint 0603M
footprint 0603L
footprint 0603_HV
footprint 0603S
pins: 1, 2

## RC0603FR-0773R2L
designator R?  ValueDisplayed: 73.2  (hidden comment: RC0603FR-0773R2L)
RES, 73.2, 1%, 0.1 W, 0603; Manufacturer: Yageo America; CompType: Resistor; Value: 73.2; Value_Code: 73R2; Tolerance_%: 1; Power_W: 0.1; Value2: 0.1W; VDC_V: 150; TempCo: 200 ppm/C; SizeArea_mm2: 1.28; SizeX_mm: 1.6; SizeY_mm: 0.8; EIA_Code: E96; U/M: EA; AEC Category: Q200
signal-integrity model Resistor
simulation model Resistor
footprint 0603
footprint 0603M
footprint 0603L
footprint 0603_HV
footprint 0603S
pins: 1, 2

## RC0603FR-0775KL
designator R?  ValueDisplayed: 75.0k  (hidden comment: RC0603FR-0775KL)
RES, 75.0 k, 1%, 0.1 W, 0603; Manufacturer: Yageo America; CompType: Resistor; Value: 75.0k; Res_ohm: 75000; Value_Code: 75k0; Tolerance_%: 1; Power_W: 0.1; Value2: 0.1W; VDC_V: 150; TempCo: 200 ppm/C; SizeArea_mm2: 1.28; SizeX_mm: 1.6; SizeY_mm: 0.8; EIA_Code: E96; U/M: EA; AEC Category: Q200; Green_Lifecycle: Active; Green_REACh: Passed
signal-integrity model Resistor
simulation model Resistor
footprint 0603
footprint 0603M
footprint 0603L
footprint 0603_HV
footprint 0603S
pins: 1, 2

## RC0603FR-0775RL
designator R?  ValueDisplayed: 75.0  (hidden comment: RC0603FR-0775RL)
RES, 75.0, 1%, 0.1 W, 0603; Manufacturer: Yageo America; CompType: Resistor; Value: 75.0; Res_ohm: 75; Value_Code: 75R0; Tolerance_%: 1; Power_W: 0.1; Value2: 0.1W; VDC_V: 150; TempCo: 200 ppm/C; SizeArea_mm2: 1.28; SizeX_mm: 1.6; SizeY_mm: 0.8; EIA_Code: E96; U/M: EA; AEC Category: Q200; Green_Lifecycle: Active; Green_REACh: Passed
signal-integrity model Resistor
simulation model Resistor
footprint 0603
footprint 0603M
footprint 0603L
footprint 0603_HV
footprint 0603S
pins: 1, 2

## RC0603FR-0776K8L
designator R?  ValueDisplayed: 76.8k  (hidden comment: RC0603FR-0776K8L)
RES, 76.8 k, 1%, 0.1 W, 0603; Manufacturer: Yageo America; CompType: Resistor; Value: 76.8k; Res_ohm: 76800; Value_Code: 76k8; Tolerance_%: 1; Power_W: 0.1; Value2: 0.1W; VDC_V: 150; TempCo: 200 ppm/C; SizeArea_mm2: 1.28; SizeX_mm: 1.6; SizeY_mm: 0.8; EIA_Code: E96; U/M: EA; AEC Category: Q200; Green_Lifecycle: Active; Green_REACh: Passed
signal-integrity model Resistor
simulation model Resistor
footprint 0603
footprint 0603M
footprint 0603L
footprint 0603_HV
footprint 0603S
pins: 1, 2

## RC0603FR-0776R8L
designator R?  ValueDisplayed: 76.8  (hidden comment: RC0603FR-0776R8L)
RES, 76.8, 1%, 0.1 W, 0603; Manufacturer: Yageo America; CompType: Resistor; Value: 76.8; Value_Code: 76R8; Tolerance_%: 1; Power_W: 0.1; Value2: 0.1W; VDC_V: 150; TempCo: 200 ppm/C; SizeArea_mm2: 1.28; SizeX_mm: 1.6; SizeY_mm: 0.8; EIA_Code: E96; U/M: EA; AEC Category: Q200; Green_Lifecycle: Active; Green_REACh: Passed
signal-integrity model Resistor
simulation model Resistor
footprint 0603
footprint 0603M
footprint 0603L
footprint 0603_HV
footprint 0603S
pins: 1, 2

## RC0603FR-0778K7L
designator R?  ValueDisplayed: 78.7k  (hidden comment: RC0603FR-0778K7L)
RES, 78.7 k, 1%, 0.1 W, 0603; Manufacturer: Yageo America; CompType: Resistor; Value: 78.7k; Res_ohm: 78700; Value_Code: 78k7; Tolerance_%: 1; Power_W: 0.1; Value2: 0.1W; VDC_V: 150; TempCo: 200 ppm/C; SizeArea_mm2: 1.28; SizeX_mm: 1.6; SizeY_mm: 0.8; EIA_Code: E96; U/M: EA; AEC Category: Q200; Green_Lifecycle: Active; Green_REACh: Passed
signal-integrity model Resistor
simulation model Resistor
footprint 0603
footprint 0603M
footprint 0603L
footprint 0603_HV
footprint 0603S
pins: 1, 2

## RC0603FR-0778R7L
designator R?  ValueDisplayed: 78.7  (hidden comment: RC0603FR-0778R7L)
RES, 78.7, 1%, 0.1 W, 0603; Manufacturer: Yageo America; CompType: Resistor; Value: 78.7; Value_Code: 78R7; Tolerance_%: 1; Power_W: 0.1; Value2: 0.1W; VDC_V: 150; TempCo: 200 ppm/C; SizeArea_mm2: 1.28; SizeX_mm: 1.6; SizeY_mm: 0.8; EIA_Code: E96; U/M: EA; AEC Category: Q200
signal-integrity model Resistor
simulation model Resistor
footprint 0603
footprint 0603M
footprint 0603L
footprint 0603_HV
footprint 0603S
pins: 1, 2

## RC0603FR-0780K6L
designator R?  ValueDisplayed: 80.6k  (hidden comment: RC0603FR-0780K6L)
RES, 80.6 k, 1%, 0.1 W, 0603; Manufacturer: Yageo America; CompType: Resistor; Value: 80.6k; Res_ohm: 80600; Value_Code: 80k6; Tolerance_%: 1; Power_W: 0.1; Value2: 0.1W; VDC_V: 150; TempCo: 200 ppm/C; SizeArea_mm2: 1.28; SizeX_mm: 1.6; SizeY_mm: 0.8; EIA_Code: E96; U/M: EA; AEC Category: Q200; Green_Lifecycle: Active; Green_REACh: Passed
signal-integrity model Resistor
simulation model Resistor
footprint 0603
footprint 0603M
footprint 0603L
footprint 0603_HV
footprint 0603S
pins: 1, 2

## RC0603FR-0780R6L
designator R?  ValueDisplayed: 80.6  (hidden comment: RC0603FR-0780R6L)
RES, 80.6, 1%, 0.1 W, 0603; Manufacturer: Yageo America; CompType: Resistor; Value: 80.6; Value_Code: 80R6; Tolerance_%: 1; Power_W: 0.1; Value2: 0.1W; VDC_V: 150; TempCo: 200 ppm/C; SizeArea_mm2: 1.28; SizeX_mm: 1.6; SizeY_mm: 0.8; EIA_Code: E96; U/M: EA; AEC Category: Q200; Green_Lifecycle: Active; Green_REACh: Passed
signal-integrity model Resistor
simulation model Resistor
footprint 0603
footprint 0603M
footprint 0603L
footprint 0603_HV
footprint 0603S
pins: 1, 2

## RC0603FR-0782K5L
designator R?  ValueDisplayed: 82.5k  (hidden comment: RC0603FR-0782K5L)
RES, 82.5 k, 1%, 0.1 W, 0603; Manufacturer: Yageo America; CompType: Resistor; Value: 82.5k; Res_ohm: 82500; Value_Code: 82k5; Tolerance_%: 1; Power_W: 0.1; Value2: 0.1W; VDC_V: 150; TempCo: 200 ppm/C; SizeArea_mm2: 1.28; SizeX_mm: 1.6; SizeY_mm: 0.8; EIA_Code: E96; U/M: EA; AEC Category: Q200
signal-integrity model Resistor
simulation model Resistor
footprint 0603
footprint 0603M
footprint 0603L
footprint 0603_HV
footprint 0603S
pins: 1, 2

## RC0603FR-0782KL
designator R?  ValueDisplayed: 82.0k  (hidden comment: RC0603FR-0782KL)
RES, 82.0 k, 1%, 0.1 W, 0603; Manufacturer: Yageo America; CompType: Resistor; Value: 82.0k; Res_ohm: 82000; Value_Code: 82k0; Tolerance_%: 1; Power_W: 0.1; Value2: 0.1W; VDC_V: 150; TempCo: 200 ppm/C; SizeArea_mm2: 1.28; SizeX_mm: 1.6; SizeY_mm: 0.8; U/M: EA; AEC Category: Q200; Green_Lifecycle: Active; Green_REACh: Passed
signal-integrity model Resistor
simulation model Resistor
footprint 0603
footprint 0603M
footprint 0603L
footprint 0603_HV
footprint 0603S
pins: 1, 2

## RC0603FR-0782R5L
designator R?  ValueDisplayed: 82.5  (hidden comment: RC0603FR-0782R5L)
RES, 82.5, 1%, 0.1 W, 0603; Manufacturer: Yageo America; CompType: Resistor; Value: 82.5; Value_Code: 82R5; Tolerance_%: 1; Power_W: 0.1; Value2: 0.1W; VDC_V: 150; TempCo: 200 ppm/C; SizeArea_mm2: 1.28; SizeX_mm: 1.6; SizeY_mm: 0.8; EIA_Code: E96; U/M: EA; AEC Category: Q200
signal-integrity model Resistor
simulation model Resistor
footprint 0603
footprint 0603M
footprint 0603L
footprint 0603_HV
footprint 0603S
pins: 1, 2

## RC0603FR-0782RL
designator R?  ValueDisplayed: 82.0  (hidden comment: RC0603FR-0782RL)
RES, 82.0, 1%, 0.1 W, 0603; Manufacturer: Yageo America; CompType: Resistor; Value: 82.0; Res_ohm: 82; Value_Code: 82R0; Tolerance_%: 1; Power_W: 0.1; Value2: 0.1W; VDC_V: 150; TempCo: 200 ppm/C; SizeArea_mm2: 1.28; SizeX_mm: 1.6; SizeY_mm: 0.8; U/M: EA; AEC Category: Q200
signal-integrity model Resistor
simulation model Resistor
footprint 0603
footprint 0603M
footprint 0603L
footprint 0603_HV
footprint 0603S
pins: 1, 2

## RC0603FR-0784K5L
designator R?  ValueDisplayed: 84.5k  (hidden comment: RC0603FR-0784K5L)
RES, 84.5 k, 1%, 0.1 W, 0603; Manufacturer: Yageo America; CompType: Resistor; Value: 84.5k; Res_ohm: 84500; Value_Code: 84k5; Tolerance_%: 1; Power_W: 0.1; Value2: 0.1W; VDC_V: 150; TempCo: 200 ppm/C; SizeArea_mm2: 1.28; SizeX_mm: 1.6; SizeY_mm: 0.8; EIA_Code: E96; U/M: EA; AEC Category: Q200; Green_Lifecycle: Active; Green_REACh: Passed
signal-integrity model Resistor
simulation model Resistor
footprint 0603
footprint 0603M
footprint 0603L
footprint 0603_HV
footprint 0603S
pins: 1, 2

## RC0603FR-0784R5L
designator R?  ValueDisplayed: 84.5  (hidden comment: RC0603FR-0784R5L)
RES, 84.5, 1%, 0.1 W, 0603; Manufacturer: Yageo America; CompType: Resistor; Value: 84.5; Value_Code: 84R5; Tolerance_%: 1; Power_W: 0.1; Value2: 0.1W; VDC_V: 150; TempCo: 200 ppm/C; SizeArea_mm2: 1.28; SizeX_mm: 1.6; SizeY_mm: 0.8; EIA_Code: E96; U/M: EA; AEC Category: Q200
signal-integrity model Resistor
simulation model Resistor
footprint 0603
footprint 0603M
footprint 0603L
footprint 0603_HV
footprint 0603S
pins: 1, 2

## RC0603FR-0786K6L
designator R?  ValueDisplayed: 86.6k  (hidden comment: RC0603FR-0786K6L)
RES, 86.6 k, 1%, 0.1 W, 0603; Manufacturer: Yageo America; CompType: Resistor; Value: 86.6k; Res_ohm: 86600; Value_Code: 86k6; Tolerance_%: 1; Power_W: 0.1; Value2: 0.1W; VDC_V: 150; TempCo: 200 ppm/C; SizeArea_mm2: 1.28; SizeX_mm: 1.6; SizeY_mm: 0.8; EIA_Code: E96; U/M: EA; AEC Category: Q200; Green_Lifecycle: Active; Green_REACh: Passed
signal-integrity model Resistor
simulation model Resistor
footprint 0603
footprint 0603M
footprint 0603L
footprint 0603_HV
footprint 0603S
pins: 1, 2

## RC0603FR-0788K7L
designator R?  ValueDisplayed: 88.7k  (hidden comment: RC0603FR-0788K7L)
RES, 88.7 k, 1%, 0.1 W, 0603; Manufacturer: Yageo America; CompType: Resistor; Value: 88.7k; Res_ohm: 88700; Value_Code: 88k7; Tolerance_%: 1; Power_W: 0.1; Value2: 0.1W; VDC_V: 150; TempCo: 200 ppm/C; SizeArea_mm2: 1.28; SizeX_mm: 1.6; SizeY_mm: 0.8; EIA_Code: E96; U/M: EA; AEC Category: Q200
signal-integrity model Resistor
simulation model Resistor
footprint 0603
footprint 0603M
footprint 0603L
footprint 0603_HV
footprint 0603S
pins: 1, 2

## RC0603FR-0788R7L
designator R?  ValueDisplayed: 88.7  (hidden comment: RC0603FR-0788R7L)
RES, 88.7, 1%, 0.1 W, 0603; Manufacturer: Yageo America; CompType: Resistor; Value: 88.7; Value_Code: 88R7; Tolerance_%: 1; Power_W: 0.1; Value2: 0.1W; VDC_V: 150; TempCo: 200 ppm/C; SizeArea_mm2: 1.28; SizeX_mm: 1.6; SizeY_mm: 0.8; EIA_Code: E96; U/M: EA; AEC Category: Q200
signal-integrity model Resistor
simulation model Resistor
footprint 0603
footprint 0603M
footprint 0603L
footprint 0603_HV
footprint 0603S
pins: 1, 2

## RC0603FR-0790K9L
designator R?  ValueDisplayed: 90.9k  (hidden comment: RC0603FR-0790K9L)
RES, 90.9 k, 1%, 0.1 W, 0603; Manufacturer: Yageo America; CompType: Resistor; Value: 90.9k; Res_ohm: 90900; Value_Code: 90k9; Tolerance_%: 1; Power_W: 0.1; Value2: 0.1W; VDC_V: 150; TempCo: 200 ppm/C; SizeArea_mm2: 1.28; SizeX_mm: 1.6; SizeY_mm: 0.8; EIA_Code: E96; U/M: EA; AEC Category: Q200; Green_Lifecycle: Active; Green_REACh: Passed
signal-integrity model Resistor
simulation model Resistor
footprint 0603
footprint 0603M
footprint 0603L
footprint 0603_HV
footprint 0603S
pins: 1, 2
